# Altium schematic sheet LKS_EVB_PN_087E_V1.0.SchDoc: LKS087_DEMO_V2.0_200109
size A4; Revision: V1.0; SheetNumber: 1; SheetTotal: 1
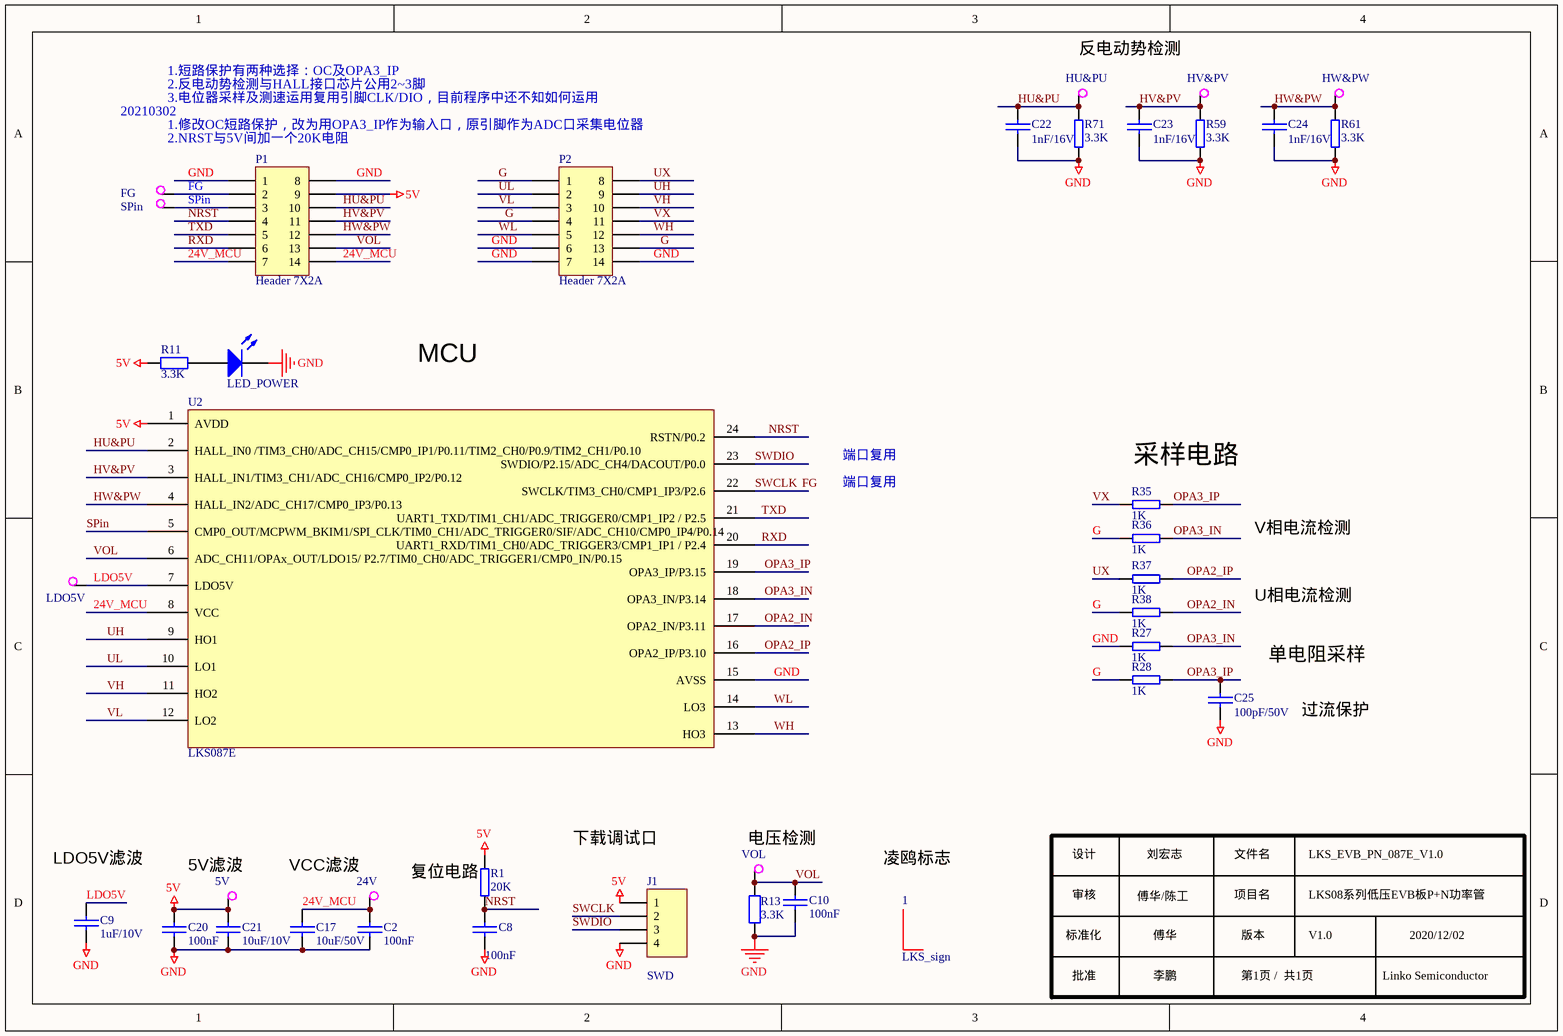
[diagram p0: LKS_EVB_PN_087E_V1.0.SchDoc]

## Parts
1  LKS_sign  [LKS_LOGO2]
5V  TestP  [TP-40]  (value not drawn)
24V  TestP  [TP-40]  (value not drawn)
C2  100nF  [0805C]
C8  100nF  [0805C]
C9  1uF/10V  [0805C]
C10  100nF  [0805C]
C17  10uF/50V  [1206]
C20  100nF  [0805C]
C21  10uF/10V  [0805C]
C22  1nF/16V  [0805C]
C23  1nF/16V  [0805C]
C24  1nF/16V  [0805C]
C25  100pF/50V  [0805C]
FG  TestP  [TP-40]  (value not drawn)
HU&PU  TestP  [TP-40]  (value not drawn)
HV&PV  TestP  [TP-40]  (value not drawn)
HW&PW  TestP  [TP-40]  (value not drawn)
J1  SWD  [SIP4-2.5]
LDO5V  TestP  [TP-40]  (value not drawn)
LED_POWER  (no value)  [0805D]
P1  Header 7X2A  [HDR2X7_CEN]
P2  Header 7X2A  [HDR2X7_CEN]
R1  20K  [0805R]
R11  3.3K  [0603R]
R13  3.3K  [0805R]
R27  1K  [0805R]
R28  1K  [0805R]
R35  1K  [0805R]
R36  1K  [0805R]
R37  1K  [0805R]
R38  1K  [0805R]
R59  3.3K  [0805R]
R61  3.3K  [0805R]
R71  3.3K  [0805R]
SPin  TestP  [TP-40]  (value not drawn)
U2  LKS087E  [LINKO-087]
VOL  TestP  [TP-40]  (value not drawn)

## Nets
5V: 5V.1 C20.1 C21.1 J1.1 P1.9 R1.1 R11.2 U2.1(AVDD)
GND: C2.2 C8.2 C9.2 C10.2 C17.1 C20.2 C21.2 C22.1 C23.1 C24.1 C25.1 J1.4 LED_POWER.2(K) P1.1 P1.8 P2.6 P2.7 P2.14 R13.2 R27.2 R59.1 R61.1 R71.1 U2.15(AVSS)
24V_MCU: 24V.1 C2.1 C17.2 P1.7 P1.14 U2.8(VCC)
FG: FG.1 J1.2 P1.2 U2.22(SWCLK/TIM3_CH0/CMP1_IP3/P2.6)  [also labelled SWCLK]
G: P2.1 P2.4 P2.13 R28.2 R36.1 R38.1
HU&PU: C22.2 HU&PU.1 P1.10 R71.2 U2.2(HALL_IN0_/TIM3_CH0/ADC_CH15/CMP0_IP1/P0.11/TIM2_CH0/P0.9/TIM2_CH1/P0.10)
HV&PV: C23.2 HV&PV.1 P1.11 R59.2 U2.3(HALL_IN1/TIM3_CH1/ADC_CH16/CMP0_IP2/P0.12)
HW&PW: C24.2 HW&PW.1 P1.12 R61.2 U2.4(HALL_IN2/ADC_CH17/CMP0_IP3/P0.13)
LDO5V: C9.1 LDO5V.1 U2.7(LDO5V)
NRST: C8.1 P1.4 R1.2 U2.24(RSTN/P0.2)
OPA2_IN: R38.2 U2.17(OPA2_IN/P3.11)
OPA2_IP: R37.2 U2.16(OPA2_IP/P3.10)
OPA3_IN: R27.1 R36.2 U2.18(OPA3_IN/P3.14)
OPA3_IP: C25.2 R28.1 R35.2 U2.19(OPA3_IP/P3.15)
RXD: P1.6 U2.20(UART1_RXD/TIM1_CH0/ADC_TRIGGER3/CMP1_IP1_/_P2.4)
SPin: P1.3 SPin.1 U2.5(CMP0_OUT/MCPWM_BKIM1/SPI_CLK/TIM0_CH1/ADC_TRIGGER0/SIF/ADC_CH10/CMP0_IP4/P0.14)
SWDIO: J1.3 U2.23(SWDIO/P2.15/ADC_CH4/DACOUT/P0.0)
TXD: P1.5 U2.21(UART1_TXD/TIM1_CH1/ADC_TRIGGER0/CMP1_IP2_/_P2.5)
UH: P2.9 U2.9(HO1)
UL: P2.2 U2.10(LO1)
UX: P2.8 R37.1
VH: P2.10 U2.11(HO2)
VL: P2.3 U2.12(LO2)
VOL: C10.1 P1.13 R13.1 U2.6(ADC_CH11/OPAx_OUT/LDO15/_P2.7/TIM0_CH0/ADC_TRIGGER1/CMP0_IN/P0.15) VOL.1
VX: P2.11 R35.1
WH: P2.12 U2.13(HO3)
WL: P2.5 U2.14(LO3)
NetLED_POWER_1: LED_POWER.1(A) R11.1

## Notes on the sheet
- 20210302
- 1.短路保护有两种选择：OC及OPA3_IP
- 2.反电动势检测与HALL接口芯片公用2~3脚
- 3.电位器采样及测速运用复用引脚CLK/DIO，目前程序中还不知如何运用
- 1.修改OC短路保护，改为用OPA3_IP作为输入口，原引脚作为ADC口采集电位器
- 2.NRST与5V间加一个20K电阻
- MCU
- 端口复用
- (near R35) 采样电路
- V相电流检测
- U相电流检测
- 过流保护
- (near C9) LDO5V滤波
- (near 5V) 5V滤波
- VCC滤波
- 复位电路
- 凌鸥标志
- 设计
- 审核
- 傅华/陈工
- 刘宏志
- 文件名
- 项目名
- LKS_EVB_PN_087E_V1.0
- LKS08系列低压EVB板P+N功率管
- 标准化
- 批准
- 傅华
- 李鹏
- 版本
- 第1页 /  共1页
- V1.0
- Linko Semiconductor
- 2020/12/02
- Labels drawn without touching a wire or pin: 下载调试口, 单电阻采样, 反电动势检测, 电压检测

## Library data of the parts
C2 C10 C17 = CAP: Capacitor
C8 C9 C20-C25 = C: Capacitor
J1 = Header 4: Header, 4-Pin
LED_POWER = LED2: Typical RED, GREEN, YELLOW, AMBER GaAs LED
P1 P2 = Header 7X2A: Header, 7-Pin, Dual row
R1 R27 R28 R35-R38 = RES2-1
R11 R13 = Res2: Resistor
R59 R61 R71 = RES/1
